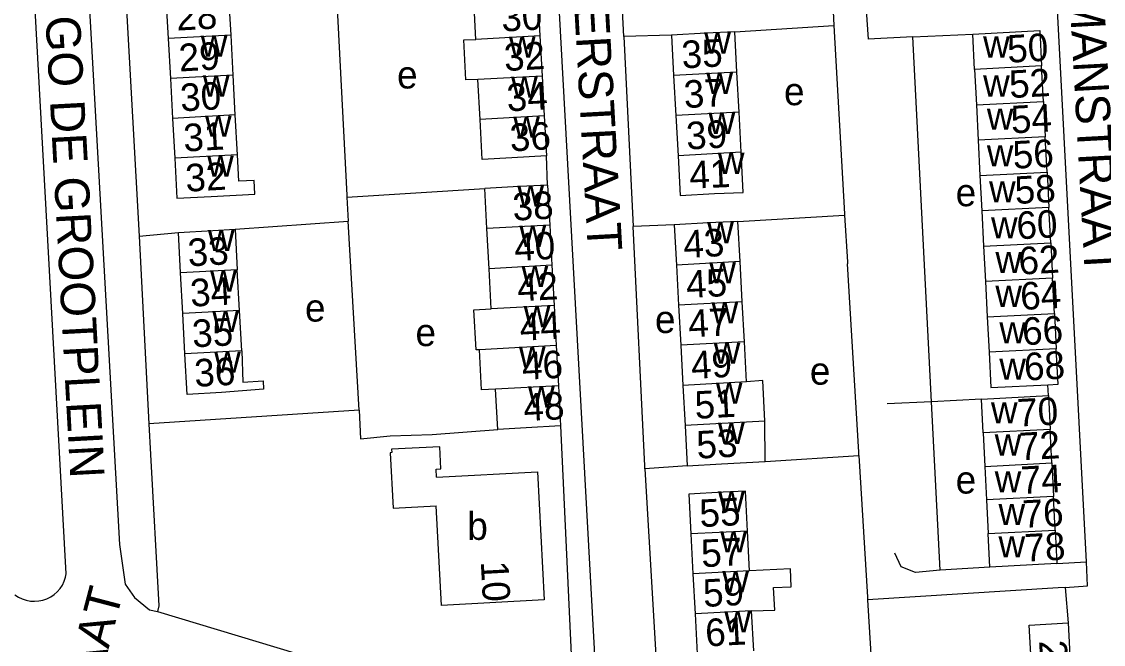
# Model space of a CAD drawing. Extents: x 157569 to 159501, y 382907 to 384670.
# Drawn here: x 158735.9 to 158892.8, y 383402.3 to 383492.8 of the extents above; entities that cross this region are included whole.
import ezdxf

# ---------------------------------------------------------------- set-up
doc = ezdxf.new("R2010")
doc.units = 0
for name, color, linetype in [('BLT_Basislijn', 7, 'Continuous'), ('BLT_Bebouwing', 7, 'Continuous'), ('BLT_Centroide', 7, 'Continuous'), ('BLT_Huisnummer', 7, 'Continuous'), ('BLT_Huisnummer_ tussenligend', 7, 'Continuous'), ('BLT_Huisnummer_reeks', 7, 'Continuous'), ('BLT_Onderverdeling_panden', 7, 'Continuous'), ('BLT_Straatnaam', 7, 'Continuous')]:
    doc.layers.add(name, color=color, linetype=linetype)

msp = doc.modelspace()

# ---------------------------------------------------------------- linework, layer by layer
at = {"layer": 'BLT_Basislijn'}
for p, q in [((158890.34, 383414.32), (158880.3, 383606.77)), ((158823.21, 383490.59), (158819.84, 383558.34)), ((158748.14, 383547.94), (158752.89, 383461.63)), ((158742.32, 383412.58), (158734.98, 383546.09)), ((158853.29, 383500.32), (158853.7, 383492.22)), ((158858.4, 383494.45), (158858.68, 383490.22)), ((158839.33, 383491.28), (158853.7, 383492.22)), ((158830.14, 383490.82), (158823.21, 383490.59)), ((158823.21, 383490.59), (158824.59, 383463)), ((158865.14, 383490.55), (158858.68, 383490.22)), ((158865.14, 383490.55), (158873.85, 383490.96)), ((158867.87, 383437.58), (158865.14, 383490.55)), ((158812.17, 383469.04), (158811.99, 383473.27)), ((158783.06, 383467.27), (158803.04, 383468.55)), ((158783.06, 383467.27), (158783.24, 383463.77)), ((158839.79, 383463.74), (158855.27, 383464.68)), ((158766.84, 383462.61), (158783.24, 383463.77)), ((158784.81, 383436.35), (158783.24, 383463.77)), ((158830.53, 383463.26), (158824.59, 383463)), ((158752.89, 383461.63), (158758.6, 383462.17)), ((158752.89, 383461.63), (158754.32, 383434.37)), ((158884.83, 383438.49), (158884.75, 383440.04)), ((158875.11, 383437.95), (158867.87, 383437.58)), ((158784.81, 383436.35), (158754.32, 383434.37)), ((158867.87, 383437.58), (158861.43, 383437.26)), ((158869.12, 383413.14), (158867.87, 383437.58)), ((158754.32, 383434.37), (158754.57, 383429.93)), ((158795.43, 383432.83), (158804.93, 383433.53)), ((158814.05, 383434.06), (158816.12, 383389.41)), ((158832.42, 383428.28), (158826.3, 383427.83)), ((158843.72, 383428.9), (158857.35, 383429.76)), ((158863.48, 383413.6), (158862.56, 383415.61)), ((158886.06, 383414.09), (158890.34, 383414.32)), ((158865.53, 383412.79), (158863.48, 383413.6)), ((158869.12, 383413.14), (158865.53, 383412.79)), ((158876.35, 383413.54), (158869.12, 383413.14)), ((158886.24, 383410.55), (158858.6, 383408.83)), ((158887.27, 383410.61), (158886.24, 383410.55)), ((158887.27, 383410.61), (158887.72, 383405.46))]:
    msp.add_line(p, q, dxfattribs=at)
for points in [[(158806.83, 383621.66), (158819.46, 383392.01), (158819.71, 383391.92), (158819.2, 383390.12), (158817.89, 383389.1)], [(158744.75, 383605.88), (158741.38, 383604.82), (158740.1, 383603.75), (158739.82, 383603.14), (158739.83, 383599), (158750.07, 383416.84), (158750.86, 383411.09), (158752.25, 383409.15), (158754.43, 383407.37), (158755.56, 383407.12)], [(158780.45, 383518.07), (158783.04, 383467.56), (158783.06, 383467.27)], [(158853.7, 383492.22), (158855.26, 383464.87), (158855.27, 383464.68)], [(158855.27, 383464.68), (158855.68, 383457.88), (158855.7, 383457.58)], [(158826.3, 383427.83), (158826.27, 383428.26), (158824.59, 383463)], [(158857.35, 383429.76), (158857.33, 383430.25), (158855.7, 383457.58)], [(158784.81, 383436.35), (158785.02, 383432.19), (158789.33, 383432.61), (158795.43, 383432.83)], [(158754.57, 383429.93), (158755.74, 383407.94), (158755.56, 383407.12)], [(158857.35, 383429.76), (158858.58, 383409.19), (158858.6, 383408.83)], [(158826.3, 383427.83), (158828.53, 383389.26)], [(158887.27, 383410.61), (158890.52, 383410.82), (158890.34, 383414.32)], [(158734.89, 383409.55), (158735.4, 383409.22), (158735.95, 383408.95), (158736.53, 383408.76), (158737.13, 383408.64), (158737.74, 383408.6), (158738.35, 383408.65), (158738.94, 383408.77), (158739.52, 383408.97), (158740.07, 383409.24), (158740.57, 383409.59), (158741.03, 383409.99), (158741.43, 383410.45), (158741.76, 383410.96), (158742.03, 383411.51), (158742.22, 383412.09), (158742.32, 383412.58)], [(158858.6, 383408.83), (158859.33, 383396.93), (158858.83, 383388.32)], [(158755.56, 383407.12), (158793.24, 383395.76), (158816.12, 383389.41)]]:
    msp.add_lwpolyline(points, dxfattribs=at)
at = {"layer": 'BLT_Bebouwing'}
for p, q in [((158756.8, 383496.12), (158757.12, 383490.32)), ((158766.24, 383490.81), (158765.92, 383496.61)), ((158801.77, 383490.17), (158801.47, 383495.97)), ((158810.72, 383496.48), (158811.04, 383490.68)), ((158839.64, 383485.45), (158839.33, 383491.28)), ((158873.85, 383490.96), (158883.58, 383491.48)), ((158883.58, 383491.48), (158883.85, 383486.33)), ((158757.12, 383490.32), (158757.43, 383484.52)), ((158766.55, 383485.01), (158766.24, 383490.81)), ((158811.04, 383490.68), (158811.36, 383484.87)), ((158830.14, 383490.82), (158830.46, 383484.95)), ((158874.11, 383485.83), (158873.85, 383490.96)), ((158884.11, 383481.19), (158883.85, 383486.33)), ((158766.86, 383479.21), (158766.55, 383485.01)), ((158811.36, 383484.87), (158811.68, 383479.07)), ((158830.46, 383484.95), (158830.77, 383479.13)), ((158839.96, 383479.62), (158839.64, 383485.45)), ((158874.11, 383485.83), (158874.38, 383480.69)), ((158757.43, 383484.52), (158757.74, 383478.72)), ((158802.37, 383478.56), (158802.07, 383484.36)), ((158874.38, 383480.69), (158874.64, 383475.56)), ((158884.11, 383481.19), (158884.38, 383476.06)), ((158757.74, 383478.72), (158758.06, 383472.92)), ((158767.18, 383473.41), (158766.86, 383479.21)), ((158811.68, 383479.07), (158811.99, 383473.27)), ((158830.77, 383479.13), (158831.09, 383473.3)), ((158840.27, 383473.8), (158839.96, 383479.62)), ((158874.64, 383475.56), (158874.9, 383470.43)), ((158884.65, 383470.93), (158884.38, 383476.06)), ((158884.65, 383470.93), (158884.91, 383465.79)), ((158874.9, 383470.43), (158875.17, 383465.29)), ((158803.36, 383462.72), (158803.04, 383468.55)), ((158812.17, 383469.04), (158812.48, 383463.21)), ((158875.17, 383465.29), (158875.43, 383460.16)), ((158885.18, 383460.66), (158884.91, 383465.79)), ((158812.48, 383463.21), (158812.8, 383457.38)), ((158830.53, 383463.26), (158830.85, 383457.42)), ((158840.11, 383457.92), (158839.79, 383463.74)), ((158758.92, 383456.29), (158758.6, 383462.17)), ((158766.84, 383462.61), (158767.15, 383456.73)), ((158803.67, 383456.89), (158803.36, 383462.72)), ((158875.43, 383460.16), (158875.69, 383455.03)), ((158885.18, 383460.66), (158885.45, 383455.53)), ((158767.47, 383450.84), (158767.15, 383456.73)), ((158803.98, 383451.06), (158803.67, 383456.89)), ((158812.8, 383457.38), (158813.11, 383451.55)), ((158830.85, 383457.42), (158831.16, 383451.59)), ((158840.42, 383452.09), (158840.11, 383457.92)), ((158759.23, 383450.4), (158758.92, 383456.29)), ((158875.69, 383455.03), (158875.96, 383449.89)), ((158885.72, 383450.39), (158885.45, 383455.53)), ((158840.73, 383446.26), (158840.42, 383452.09)), ((158759.55, 383444.52), (158759.23, 383450.4)), ((158767.79, 383444.96), (158767.47, 383450.84)), ((158813.11, 383451.55), (158813.42, 383445.72)), ((158831.16, 383451.59), (158831.48, 383445.77)), ((158885.72, 383450.39), (158885.98, 383445.26)), ((158875.96, 383449.89), (158876.22, 383444.76)), ((158813.42, 383445.72), (158813.74, 383439.89)), ((158831.48, 383445.77), (158831.79, 383439.94)), ((158841.05, 383440.44), (158840.73, 383446.26)), ((158876.22, 383444.76), (158876.48, 383439.62)), ((158886.25, 383440.12), (158885.98, 383445.26)), ((158804.93, 383433.53), (158804.61, 383439.4)), ((158813.74, 383439.89), (158814.05, 383434.06)), ((158831.79, 383439.94), (158832.11, 383434.11)), ((158876.48, 383439.62), (158884.75, 383440.04)), ((158884.75, 383440.04), (158886.25, 383440.12)), ((158875.11, 383437.95), (158884.83, 383438.49)), ((158875.36, 383433.07), (158875.11, 383437.95)), ((158884.83, 383438.49), (158885.08, 383433.56)), ((158843.72, 383428.9), (158843.71, 383434.74)), ((158832.11, 383434.11), (158832.42, 383428.28)), ((158875.36, 383433.07), (158875.61, 383428.19)), ((158885.32, 383428.68), (158885.08, 383433.56)), ((158885.32, 383428.68), (158885.57, 383423.8)), ((158875.61, 383428.19), (158875.85, 383423.31)), ((158885.82, 383418.92), (158885.57, 383423.8)), ((158875.85, 383423.31), (158876.1, 383418.43)), ((158885.82, 383418.92), (158886.06, 383414.09)), ((158832.96, 383418.38), (158833.26, 383412.58)), ((158841.46, 383413.01), (158841.16, 383418.8)), ((158876.35, 383413.54), (158876.1, 383418.43)), ((158833.26, 383412.58), (158833.57, 383406.79)), ((158886.06, 383414.09), (158876.35, 383413.54)), ((158833.57, 383406.79), (158833.87, 383400.99)), ((158842.07, 383401.42), (158841.77, 383407.21))]:
    msp.add_line(p, q, dxfattribs=at)
for points in [[(158839.33, 383491.28), (158835.13, 383491.08), (158830.14, 383490.82)], [(158802.07, 383484.36), (158800.31, 383484.33), (158800, 383490.1), (158801.77, 383490.17)], [(158811.99, 383473.27), (158807, 383472.99), (158802.68, 383472.76), (158802.37, 383478.56)], [(158831.09, 383473.3), (158831.4, 383467.52), (158836.39, 383467.79), (158840.56, 383467.97), (158840.27, 383473.8)], [(158758.06, 383472.92), (158758.37, 383467.11), (158763.36, 383467.39), (158769.7, 383467.73), (158769.6, 383469.71), (158767.38, 383469.59), (158767.18, 383473.41)], [(158812.17, 383469.04), (158807.18, 383468.77), (158803.04, 383468.55)], [(158839.79, 383463.74), (158835.52, 383463.53), (158830.53, 383463.26)], [(158758.6, 383462.17), (158763.59, 383462.44), (158766.84, 383462.61)], [(158802.28, 383445.12), (158801.78, 383445.09), (158801.46, 383450.92), (158803.98, 383451.06)], [(158767.79, 383444.96), (158767.93, 383440.43), (158770.88, 383440.59), (158770.94, 383439.39), (158764.86, 383438.9), (158759.86, 383438.63), (158759.55, 383444.52)], [(158804.61, 383439.4), (158802.6, 383439.29), (158802.28, 383445.12)], [(158843.71, 383434.74), (158843.4, 383440.64), (158841.05, 383440.44)], [(158814.05, 383434.06), (158809.06, 383433.79), (158804.93, 383433.53)], [(158796.06, 383426.61), (158795.99, 383427.79), (158796.7, 383427.83), (158796.53, 383431.02), (158789.54, 383430.67), (158789.57, 383430.18), (158789.35, 383430.17), (158789.78, 383422.12), (158795.99, 383422.45)], [(158832.42, 383428.28), (158837.42, 383428.55), (158843.72, 383428.9)], [(158796.06, 383426.61), (158810.68, 383427.39), (158811.68, 383408.8), (158796.77, 383407.99), (158795.99, 383422.45)], [(158841.16, 383418.8), (158840.86, 383424.6), (158837.65, 383424.43), (158832.66, 383424.17), (158832.96, 383418.38)], [(158841.77, 383407.21), (158845.12, 383407.3), (158844.95, 383410.58), (158847.51, 383410.71), (158847.39, 383413.31), (158841.46, 383413.01)], [(158861.59, 383383.51), (158861.54, 383384.86), (158860.92, 383395.43), (158882.54, 383396.66), (158882.06, 383405.12), (158887.72, 383405.46)], [(158887.72, 383405.46), (158888.15, 383396.98), (158888.74, 383386.37), (158888.87, 383385.03)]]:
    msp.add_lwpolyline(points, dxfattribs=at)
at = {"layer": 'BLT_Onderverdeling_panden'}
for p, q in [((158766.24, 383490.81), (158757.12, 383490.32)), ((158811.04, 383490.68), (158801.77, 383490.17)), ((158883.85, 383486.33), (158874.11, 383485.83)), ((158766.55, 383485.01), (158757.43, 383484.52)), ((158811.36, 383484.87), (158802.07, 383484.36)), ((158839.64, 383485.45), (158830.46, 383484.95)), ((158874.38, 383480.69), (158884.11, 383481.19)), ((158766.86, 383479.21), (158757.74, 383478.72)), ((158811.68, 383479.07), (158802.37, 383478.56)), ((158839.96, 383479.62), (158830.77, 383479.13)), ((158884.38, 383476.06), (158874.64, 383475.56)), ((158840.27, 383473.8), (158831.09, 383473.3)), ((158767.18, 383473.41), (158758.06, 383472.92)), ((158874.9, 383470.43), (158884.65, 383470.93)), ((158884.91, 383465.79), (158875.17, 383465.29)), ((158812.48, 383463.21), (158803.36, 383462.72)), ((158875.43, 383460.16), (158885.18, 383460.66)), ((158767.15, 383456.73), (158758.92, 383456.29)), ((158812.8, 383457.38), (158803.67, 383456.89)), ((158840.11, 383457.92), (158830.85, 383457.42)), ((158885.45, 383455.53), (158875.69, 383455.03)), ((158840.42, 383452.09), (158831.16, 383451.59)), ((158767.47, 383450.84), (158759.23, 383450.4)), ((158813.11, 383451.55), (158803.98, 383451.06)), ((158875.96, 383449.89), (158885.72, 383450.39)), ((158813.42, 383445.72), (158802.28, 383445.12)), ((158840.73, 383446.26), (158831.48, 383445.77)), ((158767.79, 383444.96), (158759.55, 383444.52)), ((158885.98, 383445.26), (158876.22, 383444.76)), ((158813.74, 383439.89), (158804.61, 383439.4)), ((158841.05, 383440.44), (158831.79, 383439.94)), ((158843.71, 383434.74), (158832.11, 383434.11)), ((158885.08, 383433.56), (158875.36, 383433.07)), ((158875.61, 383428.19), (158885.32, 383428.68)), ((158885.57, 383423.8), (158875.85, 383423.31)), ((158876.1, 383418.43), (158885.82, 383418.92)), ((158841.16, 383418.8), (158832.96, 383418.38)), ((158841.46, 383413.01), (158833.26, 383412.58)), ((158841.77, 383407.21), (158833.57, 383406.79))]:
    msp.add_line(p, q, dxfattribs=at)

# ---------------------------------------------------------------- texts
at = {"layer": 'BLT_Centroide'}
for s, p in [('w', (158834.89, 383488.12)), ('w', (158761.84, 383487.66)), ('w', (158806.56, 383487.53)), ('w', (158875.36, 383487.54)), ('w', (158762.15, 383481.88)), ('e', (158790.33, 383483.06)), ('w', (158806.87, 383481.72)), ('w', (158835.2, 383482.28)), ('w', (158875.36, 383481.88)), ('e', (158846.47, 383480.63)), ('w', (158875.9, 383477.07)), ('w', (158762.46, 383476.06)), ('w', (158807.18, 383475.91)), ('w', (158835.52, 383476.47)), ('w', (158875.9, 383471.75)), ('w', (158762.77, 383470.25)), ('w', (158836.87, 383470.66)), ('e', (158871.38, 383465.96)), ('w', (158876.22, 383466.52)), ('w', (158807.77, 383465.88)), ('w', (158876.51, 383461.29)), ('w', (158808.08, 383460.06)), ('w', (158835.32, 383460.59)), ('w', (158762.88, 383459.44)), ('w', (158877.14, 383456.26)), ('w', (158763.2, 383453.56)), ('w', (158808.39, 383454.22)), ('w', (158835.63, 383454.75)), ('w', (158877.14, 383451.34)), ('e', (158776.97, 383449.21)), ('w', (158835.95, 383448.94)), ('w', (158763.51, 383447.69)), ('w', (158808.7, 383448.38)), ('e', (158827.75, 383447.55)), ('e', (158793, 383445.65)), ('w', (158877.71, 383446.05)), ('w', (158808.01, 383442.5)), ('w', (158836.27, 383443.09)), ('w', (158763.79, 383441.78)), ('e', (158850.22, 383440.05)), ('w', (158877.71, 383440.76)), ('w', (158809.33, 383436.72)), ('w', (158836.58, 383437.28)), ('w', (158876.5, 383434.42)), ('w', (158836.89, 383431.44)), ('w', (158877.04, 383429.76)), ('e', (158871.38, 383424.24)), ('w', (158877.04, 383424.41)), ('w', (158836.91, 383421.5)), ('w', (158877.59, 383419.66)), ('b', (158800.52, 383417.52)), ('w', (158837.22, 383415.69)), ('w', (158877.59, 383414.96)), ('w', (158837.52, 383409.91)), ('w', (158837.81, 383404.09))]:
    msp.add_text(s, height=4, dxfattribs=at).set_placement(p)
at = {"layer": 'BLT_Huisnummer'}
for s, rotation, p in [('28', 3.0978, (158758.38, 383491.46)), ('30', 3.1393, (158805.55, 383491.31)), ('50', 3.0105, (158878.96, 383486.79)), ('35', 3.0969, (158831.71, 383485.96)), ('30', 3.0978, (158758.96, 383479.73)), ('54', 3.0105, (158879.49, 383476.53)), ('36', 3.1393, (158806.79, 383473.91)), ('32', 3.0978, (158759.71, 383468.06)), ('41', 2.47, (158832.82, 383468.5)), ('58', 3.0105, (158880.04, 383466.28)), ('38', 3.0787, (158807.18, 383463.86)), ('33', 3.0704, (158760.05, 383457.22)), ('43', 3.0787, (158831.96, 383458.43)), ('62', 3.0105, (158880.59, 383456.02)), ('42', 3.0787, (158807.85, 383452.14)), ('47', 3.0787, (158832.67, 383446.9)), ('36', 3.0704, (158761.01, 383439.73)), ('68', 3.0105, (158881.39, 383440.64)), ('48', 3.0787, (158808.76, 383434.74)), ('70', 3.0105, (158880.41, 383433.96)), ('53', 3.0787, (158833.87, 383429.3)), ('74', 3.0105, (158880.92, 383424.16)), ('55', 2.9802, (158834.3, 383419.36)), ('78', 3.0105, (158881.45, 383414.35)), ('10', 273.0716, (158802.47, 383414.37)), ('59', 2.9802, (158834.82, 383407.77))]:
    msp.add_text(s, height=4, rotation=rotation, dxfattribs=at).set_placement(p)
at = {"layer": 'BLT_Huisnummer_ tussenligend'}
for s, rotation, p in [('29', 3.0978, (158758.75, 383485.52)), ('32', 3.1393, (158805.95, 383485.58)), ('52', 3.0105, (158879.24, 383481.66)), ('34', 3.1393, (158806.33, 383479.72)), ('37', 3.0969, (158832.03, 383480.2)), ('39', 3.0969, (158832.37, 383474.18)), ('31', 3.0978, (158759.42, 383473.89)), ('56', 3.0105, (158879.76, 383471.4)), ('60', 3.0105, (158880.3, 383461.15)), ('40', 3.0787, (158807.43, 383458)), ('45', 3.0787, (158832.36, 383452.61)), ('34', 3.0704, (158760.41, 383451.37)), ('64', 3.0105, (158880.84, 383450.89)), ('44', 3.0787, (158808.22, 383446.41)), ('35', 3.0704, (158760.69, 383445.46)), ('66', 3.0105, (158881.11, 383445.77)), ('46', 3.0787, (158808.55, 383440.74)), ('49', 3.0787, (158833.08, 383440.88)), ('51', 3.0787, (158833.6, 383435.08)), ('72', 3.0105, (158880.68, 383429.06)), ('76', 3.0105, (158881.18, 383419.25)), ('57', 2.9802, (158834.55, 383413.54)), ('61', 2.9802, (158835.14, 383402.03))]:
    msp.add_text(s, height=4, rotation=rotation, dxfattribs=at).set_placement(p)
at = {"layer": 'BLT_Huisnummer_reeks'}
msp.add_text('2 t/m 8c', height=4, rotation=273.3601, dxfattribs=at).set_placement((158883.47, 383402.85))
at = {"layer": 'BLT_Straatnaam'}
for s, height, rotation, p in [('ANTONY MODDERMANSTRAAT', 4.9999, 273.1448, (158884.6, 383556.33)), ('TOBIAS ASSERSTRAAT', 5, 273.1822, (158813.83, 383534.67)), ('HUGO DE GROOTPLEIN', 4.9999, 273.0779, (158738.79, 383503.15)), ('JOHANNES VOETSTRAAT', 5, 75.3025, (158729.6, 383329.72))]:
    msp.add_text(s, height=height, rotation=rotation, dxfattribs=at).set_placement(p)

doc.saveas('drawing.dxf')
